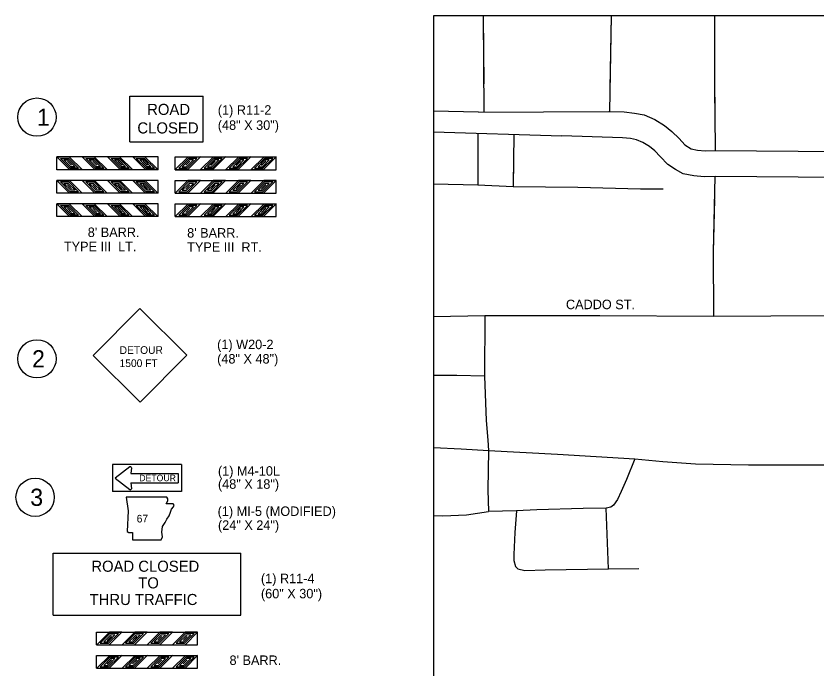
# Model space of a CAD drawing. Extents: x 988392 to 996681, y 1838707 to 1844440.
# Drawn here: x 988392 to 991180, y 1842166 to 1844440 of the extents above; entities that cross this region are included whole.
import ezdxf

# ---------------------------------------------------------------- set-up
doc = ezdxf.new("R2010")
doc.units = 0
for name, color, linetype in [('1', 7, 'Continuous'), ('21', 7, 'Continuous'), ('3', 7, 'Continuous'), ('8', 7, 'Continuous'), ('G-Border-Sheet', 7, 'Continuous'), ('Level 10', 7, 'Continuous'), ('Level 3', 7, 'Continuous'), ('Level 33', 7, 'Continuous'), ('Level 8', 7, 'Continuous'), ('R_Draft', 7, 'Continuous')]:
    doc.layers.add(name, color=color, linetype=linetype)

msp = doc.modelspace()

# ---------------------------------------------------------------- linework, layer by layer
at = {"layer": '1'}
for p, q in [((988968.8, 1842877.6), (988728.4, 1842877.6)), ((988728.4, 1842877.6), (988728.4, 1842784.1)), ((988788.6, 1842869.6), (988737.3, 1842830.1)), ((988793.9, 1842866.7), (988792.2, 1842846.6)), ((988968.8, 1842877.6), (988968.8, 1842784.1)), ((988792.2, 1842846.6), (988956.3, 1842846.6)), ((988956.3, 1842846.6), (988956.3, 1842813.6)), ((988737.3, 1842830.1), (988788.5, 1842790.6)), ((988792.2, 1842813.6), (988956.3, 1842813.6)), ((988792.2, 1842813.6), (988793.8, 1842793.5)), ((988968.8, 1842784.1), (988728.4, 1842784.1))]:
    msp.add_line(p, q, dxfattribs=at)
at = {"layer": '21'}
msp.add_lwpolyline([(988775.3, 1842764.4), (988782.4, 1842716.9), (988779.1, 1842644.9), (988785.5, 1842640.9), (988797.3, 1842640.9), (988797.3, 1842615.6), (988897.1, 1842615.5), (988901.9, 1842625.8), (988900.3, 1842642.4), (988902.7, 1842661.4), (988911.4, 1842676.4), (988917, 1842687.5), (988924.9, 1842699.4), (988929.6, 1842712), (988933.6, 1842722.3), (988940.8, 1842731), (988942.3, 1842736.6), (988939.2, 1842740.5), (988914.6, 1842740.5), (988920.2, 1842751.6), (988921, 1842758.8), (988917.7, 1842764.2)], close=True, dxfattribs=at)
msp.add_lwpolyline([(988775.3, 1842764.4), (988782.4, 1842716.9), (988779.1, 1842644.9), (988785.5, 1842640.9), (988797.3, 1842640.9), (988797.3, 1842615.6), (988897.1, 1842615.5), (988901.9, 1842625.8), (988900.3, 1842642.4), (988902.7, 1842661.4), (988911.4, 1842676.4), (988917, 1842687.5), (988924.9, 1842699.4), (988929.6, 1842712), (988933.6, 1842722.3), (988940.8, 1842731), (988942.3, 1842736.6), (988939.2, 1842740.5), (988914.6, 1842740.5), (988920.2, 1842751.6), (988921, 1842758.8), (988917.7, 1842764.2)], close=True, dxfattribs=at)
at = {"layer": '3'}
for p, q in [((988788.9, 1844001.8), (988788.9, 1844161)), ((988788.9, 1844161), (989043.8, 1844161)), ((989043.8, 1844001.8), (989043.8, 1844161)), ((988788.9, 1844001.8), (989043.8, 1844001.8)), ((988887, 1843948.7), (988534.8, 1843948.7)), ((988534.8, 1843904.5), (988534.8, 1843948.7)), ((988887, 1843904.5), (988887, 1843948.7)), ((988945.8, 1843948.7), (989297.9, 1843948.7)), ((988945.8, 1843904.5), (988945.8, 1843948.7)), ((989297.9, 1843904.5), (989297.9, 1843948.7)), ((988535.1, 1843904.6), (988534.8, 1843904.9)), ((988887, 1843904.5), (988534.8, 1843904.5)), ((988945.8, 1843904.5), (989297.9, 1843904.5)), ((989297.7, 1843904.6), (989297.9, 1843904.9)), ((988887, 1843866.7), (988534.8, 1843866.7)), ((988534.8, 1843822.6), (988534.8, 1843866.7)), ((988534.8, 1843822.6), (988534.8, 1843866.7)), ((988887, 1843822.6), (988887, 1843866.7)), ((988945.8, 1843866.7), (989297.9, 1843866.7)), ((988945.8, 1843822.6), (988945.8, 1843866.7)), ((989297.9, 1843822.6), (989297.9, 1843866.7)), ((989297.9, 1843822.6), (989297.9, 1843866.7)), ((988887, 1843822.6), (988534.8, 1843822.6)), ((988945.8, 1843822.6), (989297.9, 1843822.6)), ((988887, 1843785), (988534.8, 1843785)), ((988534.8, 1843740.9), (988534.8, 1843785)), ((988887, 1843740.9), (988887, 1843785)), ((988945.8, 1843785), (989297.9, 1843785)), ((988945.8, 1843740.9), (988945.8, 1843785)), ((989297.9, 1843740.9), (989297.9, 1843785)), ((988887, 1843740.9), (988534.8, 1843740.9)), ((988945.8, 1843740.9), (989297.9, 1843740.9)), ((988522, 1842353), (988522, 1842569.1)), ((988522, 1842569.1), (989175.1, 1842569.1)), ((989175.1, 1842353), (989175.1, 1842569.1)), ((988522, 1842353), (989175.1, 1842353)), ((988672.5, 1842294.3), (989024.6, 1842294.3)), ((988672.5, 1842250), (988672.5, 1842294.3)), ((989024.6, 1842250), (989024.6, 1842294.3)), ((988672.5, 1842250), (989024.6, 1842250)), ((989024.4, 1842250.2), (989024.6, 1842250.4)), ((988672.5, 1842212.3), (989024.6, 1842212.3)), ((988672.5, 1842168.2), (988672.5, 1842212.3)), ((989024.6, 1842168.2), (989024.6, 1842212.3)), ((989024.6, 1842168.2), (989024.6, 1842212.3)), ((988672.5, 1842168.2), (989024.6, 1842168.2))]:
    msp.add_line(p, q, dxfattribs=at)
for points in [[(988534.8, 1843948.7), (988578.1, 1843948.6), (988622.1, 1843904.6), (988578.9, 1843904.6)], [(988547, 1843943.7), (988576.1, 1843943.6), (988610, 1843909.6), (988581, 1843909.6)], [(988598, 1843914.6), (988583.1, 1843914.6), (988559.1, 1843938.6), (988574, 1843938.6)], [(988571.2, 1843933.6), (988571.9, 1843933.6), (988585.9, 1843919.6), (988585.1, 1843919.6)], [(988622.8, 1843948.7), (988666.1, 1843948.6), (988710.1, 1843904.6), (988666.9, 1843904.6)], [(988635, 1843943.7), (988664.1, 1843943.6), (988698, 1843909.6), (988669, 1843909.6)], [(988686, 1843914.6), (988671.1, 1843914.6), (988647.1, 1843938.6), (988662, 1843938.6)], [(988659.2, 1843933.6), (988659.9, 1843933.6), (988673.9, 1843919.6), (988673.1, 1843919.6)], [(988710.8, 1843948.7), (988754.1, 1843948.6), (988798.1, 1843904.6), (988754.9, 1843904.6)], [(988723, 1843943.7), (988752.1, 1843943.6), (988786, 1843909.6), (988757, 1843909.6)], [(988774, 1843914.6), (988759.1, 1843914.6), (988735.1, 1843938.6), (988750, 1843938.6)], [(988747.2, 1843933.6), (988747.9, 1843933.6), (988761.9, 1843919.6), (988761.1, 1843919.6)], [(988798.8, 1843948.7), (988842.1, 1843948.6), (988886.1, 1843904.6), (988842.9, 1843904.6)], [(988811, 1843943.7), (988840.1, 1843943.6), (988874, 1843909.6), (988845, 1843909.6)], [(988862, 1843914.6), (988847.1, 1843914.6), (988823.1, 1843938.6), (988838, 1843938.6)], [(988835.2, 1843933.6), (988835.9, 1843933.6), (988849.9, 1843919.6), (988849.1, 1843919.6)], [(989033.9, 1843948.7), (988990.6, 1843948.6), (988946.7, 1843904.6), (988989.9, 1843904.6)], [(989021.8, 1843943.7), (988992.7, 1843943.6), (988958.8, 1843909.6), (988987.8, 1843909.6)], [(988970.8, 1843914.6), (988985.7, 1843914.6), (989009.7, 1843938.6), (988994.8, 1843938.6)], [(988997.6, 1843933.6), (988996.9, 1843933.6), (988982.9, 1843919.6), (988983.6, 1843919.6)], [(989121.9, 1843948.7), (989078.6, 1843948.6), (989034.7, 1843904.6), (989077.9, 1843904.6)], [(989109.8, 1843943.7), (989080.7, 1843943.6), (989046.8, 1843909.6), (989075.8, 1843909.6)], [(989058.8, 1843914.6), (989073.7, 1843914.6), (989097.7, 1843938.6), (989082.8, 1843938.6)], [(989085.6, 1843933.6), (989084.9, 1843933.6), (989070.9, 1843919.6), (989071.6, 1843919.6)], [(989209.9, 1843948.7), (989166.6, 1843948.6), (989122.7, 1843904.6), (989165.9, 1843904.6)], [(989197.8, 1843943.7), (989168.7, 1843943.6), (989134.8, 1843909.6), (989163.8, 1843909.6)], [(989146.8, 1843914.6), (989161.7, 1843914.6), (989185.7, 1843938.6), (989170.8, 1843938.6)], [(989173.6, 1843933.6), (989172.9, 1843933.6), (989158.9, 1843919.6), (989159.6, 1843919.6)], [(989297.9, 1843948.7), (989254.6, 1843948.6), (989210.7, 1843904.6), (989253.9, 1843904.6)], [(989285.8, 1843943.7), (989256.7, 1843943.6), (989222.8, 1843909.6), (989251.8, 1843909.6)], [(989234.8, 1843914.6), (989249.7, 1843914.6), (989273.7, 1843938.6), (989258.8, 1843938.6)], [(989261.6, 1843933.6), (989260.9, 1843933.6), (989246.9, 1843919.6), (989247.6, 1843919.6)], [(988534.8, 1843866.7), (988578.1, 1843866.6), (988622.1, 1843822.6), (988578.9, 1843822.6)], [(988622.8, 1843866.7), (988666.1, 1843866.6), (988710.1, 1843822.6), (988666.9, 1843822.6)], [(988622.8, 1843866.7), (988666.1, 1843866.6), (988710.1, 1843822.6), (988666.9, 1843822.6)], [(988710.8, 1843866.7), (988754.1, 1843866.6), (988798.1, 1843822.6), (988754.9, 1843822.6)], [(988798.8, 1843866.7), (988842.1, 1843866.6), (988886.1, 1843822.6), (988842.9, 1843822.6)], [(989033.9, 1843866.7), (988990.6, 1843866.6), (988946.7, 1843822.6), (988989.9, 1843822.6)], [(989121.9, 1843866.7), (989078.6, 1843866.6), (989034.7, 1843822.6), (989077.9, 1843822.6)], [(989209.9, 1843866.7), (989166.6, 1843866.6), (989122.7, 1843822.6), (989165.9, 1843822.6)], [(989297.9, 1843866.7), (989254.6, 1843866.6), (989210.7, 1843822.6), (989253.9, 1843822.6)], [(988547, 1843861.7), (988576.1, 1843861.6), (988610, 1843827.6), (988581, 1843827.6)], [(988598, 1843832.6), (988583.1, 1843832.6), (988559.1, 1843856.7), (988574, 1843856.6)], [(988571.2, 1843851.6), (988571.9, 1843851.6), (988585.9, 1843837.6), (988585.1, 1843837.6)], [(988635, 1843861.7), (988664.1, 1843861.6), (988698, 1843827.6), (988669, 1843827.6)], [(988686, 1843832.6), (988671.1, 1843832.6), (988647.1, 1843856.7), (988662, 1843856.6)], [(988659.2, 1843851.6), (988659.9, 1843851.6), (988673.9, 1843837.6), (988673.1, 1843837.6)], [(988723, 1843861.7), (988752.1, 1843861.6), (988786, 1843827.6), (988757, 1843827.6)], [(988774, 1843832.6), (988759.1, 1843832.6), (988735.1, 1843856.7), (988750, 1843856.6)], [(988747.2, 1843851.6), (988747.9, 1843851.6), (988761.9, 1843837.6), (988761.1, 1843837.6)], [(988811, 1843861.7), (988840.1, 1843861.6), (988874, 1843827.6), (988845, 1843827.6)], [(988862, 1843832.6), (988847.1, 1843832.6), (988823.1, 1843856.7), (988838, 1843856.6)], [(988835.2, 1843851.6), (988835.9, 1843851.6), (988849.9, 1843837.6), (988849.1, 1843837.6)], [(989021.8, 1843861.7), (988992.7, 1843861.6), (988958.8, 1843827.6), (988987.8, 1843827.6)], [(988970.8, 1843832.6), (988985.7, 1843832.6), (989009.7, 1843856.7), (988994.8, 1843856.6)], [(988997.6, 1843851.6), (988996.9, 1843851.6), (988982.9, 1843837.6), (988983.6, 1843837.6)], [(989109.8, 1843861.7), (989080.7, 1843861.6), (989046.8, 1843827.6), (989075.8, 1843827.6)], [(989058.8, 1843832.6), (989073.7, 1843832.6), (989097.7, 1843856.7), (989082.8, 1843856.6)], [(989085.6, 1843851.6), (989084.9, 1843851.6), (989070.9, 1843837.6), (989071.6, 1843837.6)], [(989197.8, 1843861.7), (989168.7, 1843861.6), (989134.8, 1843827.6), (989163.8, 1843827.6)], [(989146.8, 1843832.6), (989161.7, 1843832.6), (989185.7, 1843856.7), (989170.8, 1843856.6)], [(989173.6, 1843851.6), (989172.9, 1843851.6), (989158.9, 1843837.6), (989159.6, 1843837.6)], [(989285.8, 1843861.7), (989256.7, 1843861.6), (989222.8, 1843827.6), (989251.8, 1843827.6)], [(989234.8, 1843832.6), (989249.7, 1843832.6), (989273.7, 1843856.7), (989258.8, 1843856.6)], [(989261.6, 1843851.6), (989260.9, 1843851.6), (989246.9, 1843837.6), (989247.6, 1843837.6)], [(988534.8, 1843785), (988578.1, 1843784.9), (988622.1, 1843740.9), (988578.9, 1843740.9)], [(988622.8, 1843785), (988666.1, 1843784.9), (988710.1, 1843740.9), (988666.9, 1843740.9)], [(988622.8, 1843785), (988666.1, 1843784.9), (988710.1, 1843740.9), (988666.9, 1843740.9)], [(988710.8, 1843785), (988754.1, 1843784.9), (988798.1, 1843740.9), (988754.9, 1843740.9)], [(988798.8, 1843785), (988842.1, 1843784.9), (988886.1, 1843740.9), (988842.9, 1843740.9)], [(989033.9, 1843785), (988990.6, 1843784.9), (988946.7, 1843740.9), (988989.9, 1843740.9)], [(989121.9, 1843785), (989078.6, 1843784.9), (989034.7, 1843740.9), (989077.9, 1843740.9)], [(989209.9, 1843785), (989166.6, 1843784.9), (989122.7, 1843740.9), (989165.9, 1843740.9)], [(989297.9, 1843785), (989254.6, 1843784.9), (989210.7, 1843740.9), (989253.9, 1843740.9)], [(988547, 1843780), (988576.1, 1843779.9), (988610, 1843745.9), (988581, 1843745.9)], [(988598, 1843750.9), (988583.1, 1843750.9), (988559.1, 1843775), (988574, 1843774.9)], [(988571.2, 1843769.9), (988571.9, 1843769.9), (988585.9, 1843755.9), (988585.1, 1843755.9)], [(988635, 1843780), (988664.1, 1843779.9), (988698, 1843745.9), (988669, 1843745.9)], [(988686, 1843750.9), (988671.1, 1843750.9), (988647.1, 1843775), (988662, 1843774.9)], [(988659.2, 1843769.9), (988659.9, 1843769.9), (988673.9, 1843755.9), (988673.1, 1843755.9)], [(988723, 1843780), (988752.1, 1843779.9), (988786, 1843745.9), (988757, 1843745.9)], [(988774, 1843750.9), (988759.1, 1843750.9), (988735.1, 1843775), (988750, 1843774.9)], [(988747.2, 1843769.9), (988747.9, 1843769.9), (988761.9, 1843755.9), (988761.1, 1843755.9)], [(988811, 1843780), (988840.1, 1843779.9), (988874, 1843745.9), (988845, 1843745.9)], [(988862, 1843750.9), (988847.1, 1843750.9), (988823.1, 1843775), (988838, 1843774.9)], [(988835.2, 1843769.9), (988835.9, 1843769.9), (988849.9, 1843755.9), (988849.1, 1843755.9)], [(989021.8, 1843780), (988992.7, 1843779.9), (988958.8, 1843745.9), (988987.8, 1843745.9)], [(988970.8, 1843750.9), (988985.7, 1843750.9), (989009.7, 1843775), (988994.8, 1843774.9)], [(988997.6, 1843769.9), (988996.9, 1843769.9), (988982.9, 1843755.9), (988983.6, 1843755.9)], [(989109.8, 1843780), (989080.7, 1843779.9), (989046.8, 1843745.9), (989075.8, 1843745.9)], [(989058.8, 1843750.9), (989073.7, 1843750.9), (989097.7, 1843775), (989082.8, 1843774.9)], [(989085.6, 1843769.9), (989084.9, 1843769.9), (989070.9, 1843755.9), (989071.6, 1843755.9)], [(989197.8, 1843780), (989168.7, 1843779.9), (989134.8, 1843745.9), (989163.8, 1843745.9)], [(989146.8, 1843750.9), (989161.7, 1843750.9), (989185.7, 1843775), (989170.8, 1843774.9)], [(989173.6, 1843769.9), (989172.9, 1843769.9), (989158.9, 1843755.9), (989159.6, 1843755.9)], [(989285.8, 1843780), (989256.7, 1843779.9), (989222.8, 1843745.9), (989251.8, 1843745.9)], [(989234.8, 1843750.9), (989249.7, 1843750.9), (989273.7, 1843775), (989258.8, 1843774.9)], [(989261.6, 1843769.9), (989260.9, 1843769.9), (989246.9, 1843755.9), (989247.6, 1843755.9)], [(988760.6, 1842294.3), (988717.4, 1842294.1), (988673.4, 1842250.2), (988716.6, 1842250.2)], [(988748.5, 1842289.2), (988719.4, 1842289.1), (988685.5, 1842255.2), (988714.5, 1842255.2)], [(988697.5, 1842260.2), (988712.4, 1842260.2), (988736.4, 1842284.2), (988721.5, 1842284.1)], [(988724.3, 1842279.1), (988723.6, 1842279.1), (988709.6, 1842265.2), (988710.3, 1842265.2)], [(988848.6, 1842294.3), (988805.4, 1842294.1), (988761.4, 1842250.2), (988804.6, 1842250.2)], [(988836.5, 1842289.2), (988807.4, 1842289.1), (988773.5, 1842255.2), (988802.5, 1842255.2)], [(988785.5, 1842260.2), (988800.4, 1842260.2), (988824.4, 1842284.2), (988809.5, 1842284.1)], [(988812.3, 1842279.1), (988811.6, 1842279.1), (988797.6, 1842265.2), (988798.3, 1842265.2)], [(988936.6, 1842294.3), (988893.4, 1842294.1), (988849.4, 1842250.2), (988892.6, 1842250.2)], [(988924.5, 1842289.2), (988895.4, 1842289.1), (988861.5, 1842255.2), (988890.5, 1842255.2)], [(988873.5, 1842260.2), (988888.4, 1842260.2), (988912.4, 1842284.2), (988897.5, 1842284.1)], [(988900.3, 1842279.1), (988899.6, 1842279.1), (988885.6, 1842265.2), (988886.3, 1842265.2)], [(989024.6, 1842294.3), (988981.4, 1842294.1), (988937.4, 1842250.2), (988980.6, 1842250.2)], [(989012.5, 1842289.2), (988983.4, 1842289.1), (988949.5, 1842255.2), (988978.5, 1842255.2)], [(988961.5, 1842260.2), (988976.4, 1842260.2), (989000.4, 1842284.2), (988985.5, 1842284.1)], [(988988.3, 1842279.1), (988987.6, 1842279.1), (988973.6, 1842265.2), (988974.3, 1842265.2)], [(988760.6, 1842212.3), (988717.4, 1842212.1), (988673.4, 1842168.2), (988716.6, 1842168.2)], [(988748.5, 1842207.2), (988719.4, 1842207.2), (988685.5, 1842173.2), (988714.5, 1842173.2)], [(988697.5, 1842178.2), (988712.4, 1842178.2), (988736.4, 1842202.2), (988721.5, 1842202.2)], [(988724.3, 1842197.2), (988723.6, 1842197.2), (988709.6, 1842183.2), (988710.3, 1842183.2)], [(988848.6, 1842212.3), (988805.4, 1842212.1), (988761.4, 1842168.2), (988804.6, 1842168.2)], [(988836.5, 1842207.2), (988807.4, 1842207.2), (988773.5, 1842173.2), (988802.5, 1842173.2)], [(988785.5, 1842178.2), (988800.4, 1842178.2), (988824.4, 1842202.2), (988809.5, 1842202.2)], [(988812.3, 1842197.2), (988811.6, 1842197.2), (988797.6, 1842183.2), (988798.3, 1842183.2)], [(988936.6, 1842212.3), (988893.4, 1842212.1), (988849.4, 1842168.2), (988892.6, 1842168.2)], [(988924.5, 1842207.2), (988895.4, 1842207.2), (988861.5, 1842173.2), (988890.5, 1842173.2)], [(988873.5, 1842178.2), (988888.4, 1842178.2), (988912.4, 1842202.2), (988897.5, 1842202.2)], [(988900.3, 1842197.2), (988899.6, 1842197.2), (988885.6, 1842183.2), (988886.3, 1842183.2)], [(989024.6, 1842212.3), (988981.4, 1842212.1), (988937.4, 1842168.2), (988980.6, 1842168.2)], [(989012.5, 1842207.2), (988983.4, 1842207.2), (988949.5, 1842173.2), (988978.5, 1842173.2)], [(988961.5, 1842178.2), (988976.4, 1842178.2), (989000.4, 1842202.2), (988985.5, 1842202.2)], [(988988.3, 1842197.2), (988987.6, 1842197.2), (988973.6, 1842183.2), (988974.3, 1842183.2)]]:
    msp.add_lwpolyline(points, close=True, dxfattribs=at)
for centre, start, end in [((988790.6, 1842866.9), 355.4261, 127.6147), ((988790.6, 1842793.3), 232.3888, 4.5739)]:
    msp.add_arc(centre, 3.3, start, end, dxfattribs=at)
at = {"layer": 'G-Border-Sheet'}
msp.add_lwpolyline([(995124.8, 1844439.6), (989844.9, 1844439.6), (989844.9, 1838706.8), (995124.8, 1838706.8)], close=True, dxfattribs=at)
at = {"layer": 'Level 10'}
msp.add_lwpolyline([(990002.4, 1844104.2), (989844.9, 1844107.9)], dxfattribs=at)
at = {"layer": 'Level 33'}
for points in [[(990018.3, 1844439.6), (990020.8, 1844104.3)], [(990018.3, 1844439.6), (990020.1, 1844203.4)], [(990463.6, 1844439.6), (990457.5, 1844107.1)], [(990463.6, 1844439.6), (990459, 1844187.1)], [(990823.2, 1844439.6), (990824, 1844220.1), (990825.6, 1843970.8)], [(990823.2, 1844439.6), (990824, 1844220.1), (990825.1, 1844050.8)], [(989999.5, 1844031.2), (989999.5, 1843850.7)], [(990124.5, 1844027.2), (990122.7, 1843845)], [(989999.5, 1843954.1), (989999.5, 1843850.7)], [(990123.7, 1843948.5), (990122.7, 1843845)], [(990824.8, 1843880.8), (990818.5, 1843618.1), (990820.1, 1843394.4)], [(990644.5, 1843837.1), (990565.8, 1843837.1), (990347.6, 1843842.8), (990122.7, 1843845), (989999.5, 1843850.7), (989844.9, 1843854.5)], [(990644.5, 1843837.1), (990565.8, 1843837.1), (990347.6, 1843842.8), (990122.7, 1843845), (989999.5, 1843850.7), (989844.9, 1843854.5)], [(990822.9, 1843800.8), (990818.5, 1843618.1), (990820.1, 1843394.4)], [(989844.9, 1843393.7), (990024.3, 1843396.6), (990424.5, 1843396.6), (990820.1, 1843394.4)], [(989844.9, 1843393.7), (990024.3, 1843396.6), (990424.5, 1843396.6), (990820.1, 1843394.4)], [(990024.3, 1843396.6), (990023.5, 1843185.5), (990029, 1843030.5), (990034.7, 1842962.7), (990036.9, 1842926.5)], [(990024.3, 1843396.6), (990023.5, 1843185.5), (990029, 1843030.5), (990034.7, 1842962.7), (990036.9, 1842926.5)], [(990820.1, 1843394.4), (991218.6, 1843396.4)], [(990820.1, 1843394.4), (991218.6, 1843396.4)], [(990023.5, 1843185.5), (989926.2, 1843187.8), (989844.9, 1843187.8)], [(990023.5, 1843185.5), (989926.2, 1843187.8), (989844.9, 1843187.8)], [(989844.9, 1842937.4), (989942, 1842932.1), (990036.9, 1842926.5)], [(989844.9, 1842937.4), (989942, 1842932.1), (990036.9, 1842926.5)], [(990036.9, 1842926.5), (990034.7, 1842789.6), (990036.9, 1842713.8)], [(990036.9, 1842926.5), (990034.7, 1842789.6), (990036.9, 1842713.8)], [(990036.9, 1842926.5), (990276.5, 1842914), (990546.7, 1842897.1), (990643.6, 1842888), (990757.8, 1842880.1), (990942, 1842876.7), (991205, 1842876.7), (991452.9, 1842875.6), (991625.8, 1842876.7)], [(990036.9, 1842926.5), (990276.5, 1842914), (990546.7, 1842897.1), (990643.6, 1842888), (990757.8, 1842880.1), (990942, 1842876.7), (991205, 1842876.7), (991452.9, 1842875.6), (991625.8, 1842876.7)], [(990546.7, 1842897.1), (990517.1, 1842825.9), (990498.6, 1842783.3), (990485.7, 1842755.8), (990471.7, 1842736.2), (990462.8, 1842729.5), (990446.5, 1842725.5), (990366.4, 1842724.4), (990205.1, 1842719.9), (990134.4, 1842716.9), (990036.9, 1842713.8)], [(990546.7, 1842897.1), (990517.1, 1842825.9), (990498.6, 1842783.3), (990485.7, 1842755.8), (990471.7, 1842736.2), (990462.8, 1842729.5), (990446.5, 1842725.5), (990366.4, 1842724.4), (990205.1, 1842719.9), (990134.4, 1842716.9), (990036.9, 1842713.8)], [(990454.1, 1842515.1), (990446.5, 1842725.5)], [(990454.1, 1842515.1), (990446.5, 1842725.5)], [(989844.9, 1842700.3), (989877.5, 1842699.2), (989959.8, 1842703.1), (990036.9, 1842713.8)], [(989844.9, 1842700.3), (989877.5, 1842699.2), (989959.8, 1842703.1), (990036.9, 1842713.8)], [(990134.4, 1842716.9), (990128.8, 1842641.2), (990124.9, 1842565), (990125.4, 1842543.7), (990131, 1842522.4), (990138.9, 1842514.5), (990163, 1842508.9), (990233.5, 1842510.6), (990454.1, 1842515.1)], [(990134.4, 1842716.9), (990128.8, 1842641.2), (990124.9, 1842565), (990125.4, 1842543.7), (990131, 1842522.4), (990138.9, 1842514.5), (990163, 1842508.9), (990233.5, 1842510.6), (990454.1, 1842515.1)], [(990454.1, 1842515.1), (990560.5, 1842516.2)], [(990454.1, 1842515.1), (990560.5, 1842516.2)]]:
    msp.add_lwpolyline(points, dxfattribs=at)
at = {"layer": 'Level 8'}
for p, q in [((988661.1, 1843257.3), (988823.3, 1843420.6)), ((988986.5, 1843258.4), (988823.3, 1843420.6)), ((988824.4, 1843095.1), (988661.1, 1843257.3)), ((988824.4, 1843095.1), (988986.5, 1843258.4))]:
    msp.add_line(p, q, dxfattribs=at)
for centre in [(988465.3, 1844087.4), (988465.3, 1843245.8), (988459, 1842763.7)]:
    msp.add_circle(centre, 66.7, dxfattribs=at)
at = {"layer": 'R_Draft'}
msp.add_line((990002.4, 1844104.2), (990454.1, 1844107.2), dxfattribs=at)
for points in [[(990454.1, 1844107.2), (990454.2, 1844107.2), (990509.5, 1844105.6), (990544.8, 1844101.8), (990578.6, 1844095), (990615.7, 1844079.5), (990648.9, 1844058.4), (990675.4, 1844037.5), (990699.9, 1844013.1), (990720, 1843991.1), (990742, 1843976.7), (990764, 1843972.4), (990790.8, 1843970.1), (990825.6, 1843970.8), (992411.3, 1843958.3)], [(989844.9, 1844036.3), (990291.8, 1844021.8)], [(990826.7, 1843880.8), (990787.7, 1843880), (990751.5, 1843883.2), (990714.4, 1843890.4), (990687.5, 1843904.8), (990661.3, 1843922), (990634.9, 1843950.8), (990615.5, 1843970.2), (990596.8, 1843984.9), (990573.9, 1843999.4), (990552.1, 1844008.6), (990531.1, 1844012.8), (990503.4, 1844015.8), (990291.8, 1844021.8)], [(992410.6, 1843868.3), (990826.7, 1843880.8)]]:
    msp.add_lwpolyline(points, dxfattribs=at)

# ---------------------------------------------------------------- texts
at = {"layer": '3'}
for s, height, p in [('ROAD', 38.59, (988848.9, 1844095.1)), ('CLOSED', 38.78, (988814.7, 1844030.5))]:
    msp.add_text(s, height=height, rotation=360, dxfattribs=at).set_placement(p)
for s, height, p in [('DETOUR', 22.56, (988821.5, 1842819.6)), ('ROAD CLOSED', 38.586, (988654.6, 1842504.3)), ('TO', 38.59, (988817.9, 1842446.4)), ('THRU TRAFFIC', 38.586, (988648.5, 1842388.5))]:
    msp.add_text(s, height=height, dxfattribs=at).set_placement(p)
at = {"layer": '8'}
for s, p in [('(1) R11-2', (989094.7, 1844095.9)), ('(48" X 30")', (989094.7, 1844043.1)), ("8' BARR.", (988988, 1843667.9)), ('TYPE III  LT.', (988559, 1843620.5)), ('TYPE III  RT.', (988988, 1843618.4)), ("8' BARR.", (989135.5, 1842179.8))]:
    msp.add_text(s, height=33, rotation=360, dxfattribs=at).set_placement(p)
for s, height, p in [("8' BARR.", 33, (988642.1, 1843670)), ('67', 26.68, (988812.3, 1842675.9)), ('(1) R11-4', 33, (989244.8, 1842464.6)), ('(60" X 30")', 33, (989244.8, 1842411.8))]:
    msp.add_text(s, height=height, dxfattribs=at).set_placement(p)
at = {"layer": 'Level 3'}
for s, height, rotation, p in [('DETOUR', 26.68, 0.2009, (988753, 1843262.7)), ('1500 FT', 26.67, 0.2001, (988752.8, 1843217))]:
    msp.add_text(s, height=height, rotation=rotation, dxfattribs=at).set_placement(p)
at = {"layer": 'Level 8'}
for s, height, p in [('1', 60, (988465.3, 1844057.4)), ('(1) W20-2', 33, (989092.3, 1843279.5)), ('2', 60, (988448.3, 1843215.8)), ('(48" X 48")', 33, (989092.4, 1843229.4)), ('3', 60, (988442, 1842733.7))]:
    msp.add_text(s, height=height, dxfattribs=at).set_placement(p)
for s, height, rotation, p in [('(1) M4-10L', 33, 0, (989095.2, 1842838.9)), ('(48" X 18")', 32.999, 0, (989095.2, 1842793.3)), ('(1) MI-5 (MODIFIED)', 33, 360, (989094.1, 1842698.7)), ('(24" X 24")', 32.999, 0, (989095.3, 1842650.3))]:
    msp.add_text(s, height=height, rotation=rotation, dxfattribs=at).set_placement(p)
at = {"layer": 'R_Draft'}
msp.add_text('CADDO ST.', height=33, rotation=360, dxfattribs=at).set_placement((990306.4, 1843418.7))

doc.saveas('drawing.dxf')
